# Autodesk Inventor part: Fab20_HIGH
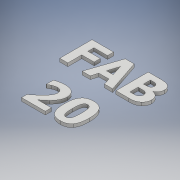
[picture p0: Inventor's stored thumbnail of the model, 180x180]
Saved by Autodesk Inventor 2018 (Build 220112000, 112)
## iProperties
Created: 2020-11
Part Number: Fab20_HIGH
Material: Genérico
Document SubType Name: Modeling
Designer: ULISES
Density: 1 g/cm^3
Appearance: Valor por defecto
Author: ULISES
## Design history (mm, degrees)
sketch "Boceto1"
  geometry: L1 (0, 0)-(60, 0); L2 (60, 0)-(60, 60); L3 (60, 60)-(0, 60); L4 (0, 60)-(0, 0); L5 (-0.169, 58.552)-(60, 58.552); L6 (60, 58.552)-(60, 0); L7 (60, 0)-(-0.169, 0); L8 (-0.169, 0)-(-0.169, 58.552)
  constraints: 8 end point, 2 parallel, 1 coincident, 1 horizontal, 1 perpendicular, 2 other
  dimensions: "d0" = 60 distance of L3.end L1.start; "d1" = 60 distance of L2.end L3.end
extrude "Extrusión1" new body sketch "Boceto1" distance "d2" = 2; taper "d3" = 0 deg
node "Sólido1"
